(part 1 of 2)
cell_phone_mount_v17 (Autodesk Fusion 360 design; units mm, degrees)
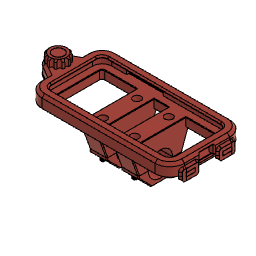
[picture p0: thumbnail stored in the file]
sketch "Skizze1" plane through (0, 0, 0) normal (0, 0, 1) x axis (1, 0, 0)
  line L1 (-75.65, 36.95) -> (75.65, 36.95)
  line L2 (-75.65, -36.95) -> (-75.65, 36.95)
  line L3 (75.65, -36.95) -> (-75.65, -36.95)
  line L4 (75.65, 36.95) -> (75.65, -36.95)
  line L5 (-75.65, -36.95) -> (75.65, 36.95)
  line L6 (75.65, -36.95) -> (-75.65, 36.95)
  point P1 (0, 0)
  point P2 (0, 0)
  point P7 (0, 0)
  point P3 (75.65, 36.95)
  point P6 (75.65, -36.95)
  point P5 (-75.65, -36.95)
  coincident P1 P2
  horizontal L1
  perpendicular L1 L2
  parallel L1 L3
  parallel L2 L4
  coincident L5 P7
  coincident L6 P7
  coincident P2 P7
  dimension "d2" distance P3 P6 = 73.9
  dimension "d3" distance P5 P6 = 151.3
extrude "Extrusion1" new body sketch "Skizze1" profile of L1 L2 L3 L4 along normal blind 9.3
fillet "Abrundung1" radius 11
component_from_bodies "Körper->Berechn"
sketch "Skizze1" plane through (0, 0, 9.3) normal (0, 0, 1) x axis (-1, 0, 0)
  line L1 (75.65, 25.95) -> (75.65, -25.95)
  line L2 (-64.65, 36.95) -> (64.65, 36.95)
  line L3 (-75.65, -25.95) -> (-75.65, 25.95)
  line L4 (64.65, -36.95) -> (-64.65, -36.95)
  line L5 (-64.65, 32.15) -> (64.65, 32.15)
  line L6 (-70.85, -25.95) -> (-70.85, 25.95)
  line L7 (64.65, -32.15) -> (-64.65, -32.15)
  line L8 (70.85, 25.95) -> (70.85, -25.95)
  line L9 (64.65, -40.25) -> (-64.65, -40.25)
  line L10 (78.95, 25.95) -> (78.95, -25.95)
  line L11 (-64.65, 40.25) -> (64.65, 40.25)
  line L12 (-78.95, -25.95) -> (-78.95, 25.95)
  arc A1 centre (64.65, -25.95) radius 11 clockwise from (75.65, -25.95) to (64.65, -36.95)
  arc A2 centre (64.65, 25.95) radius 11 clockwise from (64.65, 36.95) to (75.65, 25.95)
  arc A3 centre (-64.65, 25.95) radius 11 clockwise from (-75.65, 25.95) to (-64.65, 36.95)
  arc A4 centre (-64.65, -25.95) radius 11 clockwise from (-64.65, -36.95) to (-75.65, -25.95)
  arc A5 centre (-64.65, 25.95) radius 6.2 clockwise from (-70.85, 25.95) to (-64.65, 32.15)
  arc A6 centre (-64.65, -25.95) radius 6.2 clockwise from (-64.65, -32.15) to (-70.85, -25.95)
  arc A7 centre (64.65, -25.95) radius 6.2 clockwise from (70.85, -25.95) to (64.65, -32.15)
  arc A8 centre (64.65, 25.95) radius 6.2 clockwise from (64.65, 32.15) to (70.85, 25.95)
  arc A9 centre (64.65, -25.95) radius 14.3 clockwise from (78.95, -25.95) to (64.65, -40.25)
  arc A10 centre (64.65, 25.95) radius 14.3 clockwise from (64.65, 40.25) to (78.95, 25.95)
  arc A11 centre (-64.65, 25.95) radius 14.3 clockwise from (-78.95, 25.95) to (-64.65, 40.25)
  arc A12 centre (-64.65, -25.95) radius 14.3 clockwise from (-64.65, -40.25) to (-78.95, -25.95)
  point P1 (0, 0)
  point P14 (0, 0)
  point P15 (0, 0)
  coincident P1 P14
  coincident P1 P15
  dimension "d15" = -4.8
  dimension "d16" = 3.3
extrude "Extrusion1" new body sketch "Skizze1" along normal blind 2
sketch "Skizze2" plane through (0, 0, 9.3) normal (0, 0, -1) x axis (1, 0, 0)
  line L1 (64.65, 32.15) -> (-64.65, 32.15)
  line L2 (70.85, -25.95) -> (70.85, 25.95)
  line L3 (-64.65, -32.15) -> (64.65, -32.15)
  line L4 (-70.85, 25.95) -> (-70.85, -25.95)
  line L5 (78.95, 25.95) -> (78.95, -25.95)
  line L6 (-64.65, 40.25) -> (64.65, 40.25)
  line L7 (-78.95, -25.95) -> (-78.95, 25.95)
  line L8 (64.65, -40.25) -> (-64.65, -40.25)
  line L9 (64.65, -37.05) -> (-64.65, -37.05)
  line L10 (75.75, 25.95) -> (75.75, -25.95)
  line L11 (-64.65, 37.05) -> (64.65, 37.05)
  line L12 (-75.75, -25.95) -> (-75.75, 25.95)
  arc A1 centre (-64.65, 25.95) radius 6.2 clockwise from (-70.85, 25.95) to (-64.65, 32.15)
  arc A2 centre (64.65, 25.95) radius 6.2 clockwise from (64.65, 32.15) to (70.85, 25.95)
  arc A3 centre (64.65, -25.95) radius 6.2 clockwise from (70.85, -25.95) to (64.65, -32.15)
  arc A4 centre (-64.65, -25.95) radius 6.2 clockwise from (-64.65, -32.15) to (-70.85, -25.95)
  arc A5 centre (64.65, -25.95) radius 14.3 clockwise from (78.95, -25.95) to (64.65, -40.25)
  arc A6 centre (64.65, 25.95) radius 14.3 clockwise from (64.65, 40.25) to (78.95, 25.95)
  arc A7 centre (-64.65, 25.95) radius 14.3 clockwise from (-78.95, 25.95) to (-64.65, 40.25)
  arc A8 centre (-64.65, -25.95) radius 14.3 clockwise from (-64.65, -40.25) to (-78.95, -25.95)
  arc A9 centre (64.65, -25.95) radius 11.1 clockwise from (75.75, -25.95) to (64.65, -37.05)
  arc A10 centre (64.65, 25.95) radius 11.1 clockwise from (64.65, 37.05) to (75.75, 25.95)
  arc A11 centre (-64.65, 25.95) radius 11.1 clockwise from (-75.75, 25.95) to (-64.65, 37.05)
  arc A12 centre (-64.65, -25.95) radius 11.1 clockwise from (-64.65, -37.05) to (-75.75, -25.95)
  dimension "d19" = -3.2
extrude "Extrusion2" add sketch "Skizze2" profile of A5 L5 A6 L6 A7 L7 A8 L8 A12 L9 L12 A9 L11 L10 A10 A11 to an object
sketch "Skizze1" plane through (0, 0, 0) normal (0, 0, -1) x axis (1, 0, 0)
  line L1 (64.65, -36.95) -> (-64.65, -36.95)
  line L2 (75.65, 25.95) -> (75.65, -25.95)
  line L3 (-64.65, 36.95) -> (64.65, 36.95)
  line L4 (-75.65, -25.95) -> (-75.65, 25.95)
  line L5 (-64.65, -37.05) -> (64.65, -37.05)
  line L6 (-75.75, 25.95) -> (-75.75, -25.95)
  line L7 (64.65, 37.05) -> (-64.65, 37.05)
  line L8 (75.75, -25.95) -> (75.75, 25.95)
  line L9 (64.65, -40.25) -> (-64.65, -40.25)
  line L10 (78.95, 25.95) -> (78.95, -25.95)
  line L11 (-64.65, 40.25) -> (64.65, 40.25)
  line L12 (-78.95, -25.95) -> (-78.95, 25.95)
  line L13 (64.65, -28.95) -> (-64.65, -28.95)
  line L14 (67.65, 25.95) -> (67.65, -25.95)
  line L15 (-64.65, 28.95) -> (64.65, 28.95)
  line L16 (-67.65, -25.95) -> (-67.65, 25.95)
  line L17 (-28.15, -28.95) -> (-28.15, 28.95)
  line L18 (-8.15, -28.95) -> (-8.15, 28.95)
  line L19 (8.15, -28.95) -> (8.15, 28.95)
  line L20 (28.15, -28.95) -> (28.15, 28.95)
  arc A1 centre (-64.65, -25.95) radius 11 clockwise from (-64.65, -36.95) to (-75.65, -25.95)
  arc A2 centre (64.65, -25.95) radius 11 clockwise from (75.65, -25.95) to (64.65, -36.95)
  arc A3 centre (64.65, 25.95) radius 11 clockwise from (64.65, 36.95) to (75.65, 25.95)
  arc A4 centre (-64.65, 25.95) radius 11 clockwise from (-75.65, 25.95) to (-64.65, 36.95)
  arc A5 centre (-64.65, -25.95) radius 11.1 clockwise from (-64.65, -37.05) to (-75.75, -25.95)
  arc A6 centre (-64.65, 25.95) radius 11.1 clockwise from (-75.75, 25.95) to (-64.65, 37.05)
  arc A7 centre (64.65, 25.95) radius 11.1 clockwise from (64.65, 37.05) to (75.75, 25.95)
  arc A8 centre (64.65, -25.95) radius 11.1 clockwise from (75.75, -25.95) to (64.65, -37.05)
  arc A9 centre (-64.65, -25.95) radius 14.3 clockwise from (-64.65, -40.25) to (-78.95, -25.95)
  arc A10 centre (64.65, -25.95) radius 14.3 clockwise from (78.95, -25.95) to (64.65, -40.25)
  arc A11 centre (64.65, 25.95) radius 14.3 clockwise from (64.65, 40.25) to (78.95, 25.95)
  arc A12 centre (-64.65, 25.95) radius 14.3 clockwise from (-78.95, 25.95) to (-64.65, 40.25)
  arc A13 centre (64.65, -25.95) radius 3 clockwise from (67.65, -25.95) to (64.65, -28.95)
  arc A14 centre (64.65, 25.95) radius 3 clockwise from (64.65, 28.95) to (67.65, 25.95)
  arc A15 centre (-64.65, 25.95) radius 3 clockwise from (-67.65, 25.95) to (-64.65, 28.95)
  arc A16 centre (-64.65, -25.95) radius 3 clockwise from (-64.65, -28.95) to (-67.65, -25.95)
  point P46 (-28.15, 28.95)
  point P47 (-28.15, -28.95)
  point P48 (-8.15, 28.95)
  point P49 (-8.15, -28.95)
  point P50 (8.15, 28.95)
  point P51 (8.15, -28.95)
  point P52 (28.15, 28.95)
  point P53 (28.15, -28.95)
  coincident L15 P46
  coincident L13 P47
  perpendicular L13 L17
  coincident L15 P48
  coincident L13 P49
  perpendicular L13 L18
  coincident L15 P50
  coincident L13 P51
  perpendicular L13 L19
  coincident L15 P52
  coincident L13 P53
  perpendicular L13 L20
  dimension "d22" = -8
  dimension "d25" distance L17 L18 = 20
  dimension "d26" distance L19 L20 = 20 (= "d25")
  dimension "d27" distance L16 L17 = 39.5
  dimension "d28" distance L14 L20 = 39.5 (= "d27")
  dimension "d132" distance L17 L20 = 56.3
extrude "Extrusion1" new body sketch "Skizze1" along normal blind 2
sketch "Skizze2" plane through (0, 0, -2) normal (0, 0, -1) x axis (1, 0, 0)
  line L1 (28.15, 28.95) -> (28.15, -28.95)
  line L2 (64.65, 28.95) -> (28.15, 28.95)
  line L3 (67.65, -25.95) -> (67.65, 25.95)
  line L4 (28.15, -28.95) -> (64.65, -28.95)
  line L5 (-28.15, 28.95) -> (-64.65, 28.95)
  line L6 (-28.15, -28.95) -> (-28.15, 28.95)
  line L7 (-64.65, -28.95) -> (-28.15, -28.95)
  line L8 (-67.65, 25.95) -> (-67.65, -25.95)
  line L9 (-8.15, 28.95) -> (-8.15, -28.95)
  line L10 (8.15, 28.95) -> (-8.15, 28.95)
  line L11 (8.15, -28.95) -> (8.15, 28.95)
  line L12 (-8.15, -28.95) -> (8.15, -28.95)
  line L13 (-78.95, -25.95) -> (-78.95, 25.95)
  line L14 (64.65, -40.25) -> (-64.65, -40.25)
  line L15 (78.95, 25.95) -> (78.95, -25.95)
  line L16 (-64.65, 40.25) -> (64.65, 40.25)
  line L17 (-122.0069, 0) -> (0, 0)
  line L18 (-8.15, 25) -> (-28.15, 25)
  line L19 (28.15, 25) -> (8.15, 25)
  line L20 (-8.15, -25) -> (-28.15, -25)
  line L21 (28.15, -25) -> (8.15, -25)
  arc A1 centre (64.65, 25.95) radius 3 clockwise from (64.65, 28.95) to (67.65, 25.95)
  arc A2 centre (64.65, -25.95) radius 3 clockwise from (67.65, -25.95) to (64.65, -28.95)
  arc A3 centre (-64.65, 25.95) radius 3 clockwise from (-67.65, 25.95) to (-64.65, 28.95)
  arc A4 centre (-64.65, -25.95) radius 3 clockwise from (-64.65, -28.95) to (-67.65, -25.95)
  arc A5 centre (-64.65, -25.95) radius 14.3 clockwise from (-64.65, -40.25) to (-78.95, -25.95)
  arc A6 centre (64.65, -25.95) radius 14.3 clockwise from (78.95, -25.95) to (64.65, -40.25)
  arc A7 centre (64.65, 25.95) radius 14.3 clockwise from (64.65, 40.25) to (78.95, 25.95)
  arc A8 centre (-64.65, 25.95) radius 14.3 clockwise from (-78.95, 25.95) to (-64.65, 40.25)
  point P1 (0, 0)
  point P30 (0, 0)
  point P32 (-28.15, 25)
  point P33 (-8.15, 25)
  point P34 (8.15, 25)
  point P35 (28.15, 25)
  point P36 (-28.15, -25)
  point P37 (-8.15, -25)
  point P38 (8.15, -25)
  point P39 (28.15, -25)
  coincident P1 P30
  perpendicular L8 L17
  coincident L6 P32
  coincident L9 P33
  perpendicular L9 L18
  coincident L11 P34
  coincident L1 P35
  perpendicular L11 L19
  coincident L6 P36
  coincident L9 P37
  perpendicular L9 L20
  coincident L11 P38
  coincident L1 P39
  perpendicular L1 L21
  symmetric L17 L18 L20
  collinear L18 L19
  collinear L20 L21
  dimension "d29" distance L18 L20 = 50
extrude "Extrusion2" add sketch "Skizze2" profile of L1 L6 L9 L11 L18 L19 L20 L21 along normal blind 30
sketch "Skizze1" plane through (0, 0, -32) normal (0, 0, -1) x axis (1, 0, 0)
  line L1 (-28.15, -25) -> (-28.15, 25)
  line L2 (-8.15, -25) -> (-28.15, -25)
  line L3 (-8.15, 25) -> (-8.15, -25)
  line L4 (-28.15, 25) -> (-8.15, 25)
  line L5 (8.15, -25) -> (8.15, 25)
  line L6 (28.15, -25) -> (8.15, -25)
  line L7 (28.15, 25) -> (28.15, -25)
  line L8 (8.15, 25) -> (28.15, 25)
extrude "Extrusion1" new body sketch "Skizze1" along normal blind 18
sketch "Skizze2" plane through (-28.15, 0, 0) normal (-1, 0, 0) x axis (0, -1, 0)
  line L1 (-25, -32) -> (25, -32)
  line L2 (-25, -50) -> (-25, -32)
  line L3 (25, -50) -> (-25, -50)
  line L4 (25, -32) -> (25, -50)
  circle C1 centre (0, -32) radius 14
  point P6 (0, -32)
  midpoint L1 P6
  dimension "d34" diameter C1 = 28
extrude "Extrusion2" cut sketch "Skizze2" profile of L1 C1 no distance stored
sketch "Skizze3" plane through (-28.15, 0, 0) normal (-1, 0, 0) x axis (0, -1, 0)
  line L1 (-28.95, 0) -> (28.95, 0)
  line L2 (-28.95, -2) -> (-28.95, 0)
  line L3 (-25, -2) -> (-28.95, -2)
  line L4 (-25, -32) -> (-25, -2)
  line L5 (25, -32) -> (-25, -32)
  line L6 (25, -2) -> (25, -32)
  line L7 (28.95, -2) -> (25, -2)
  line L8 (28.95, 0) -> (28.95, -2)
  arc A1 centre (0, -32) radius 14 clockwise from (14, -32) to (-14, -32)
  circle C1 centre (0, -32) radius 14
  point P11 (14, -32)
  concentric A1 C1
  coincident P11 C1
extrude "Extrusion3" cut sketch "Skizze3" profile of L5 C1 no distance stored
sketch "Skizze4" plane through (0, 0, -32) normal (0, 0, -1) x axis (1, 0, 0)
  line L1 (-28.15, -14) -> (-8.15, -14)
  line L2 (-28.15, -25) -> (-28.15, -14)
  line L3 (-8.15, -25) -> (-28.15, -25)
  line L4 (-8.15, -14) -> (-8.15, -25)
  line L5 (-28.15, 25) -> (-8.15, 25)
  line L6 (-8.15, 14) -> (-28.15, 14)
  line L7 (-8.15, 25) -> (-8.15, 14)
  line L8 (-28.15, 25) -> (-8.15, 25)
  line L9 (-28.15, 14) -> (-28.15, 25)
  line L10 (8.15, -14) -> (28.15, -14)
  line L11 (8.15, -25) -> (8.15, -14)
  line L12 (28.15, -25) -> (8.15, -25)
  line L13 (28.15, -14) -> (28.15, -25)
  line L14 (28.15, 14) -> (8.15, 14)
  line L15 (28.15, 14) -> (8.15, 14)
  line L16 (28.15, 25) -> (28.15, 14)
  line L17 (8.15, 25) -> (28.15, 25)
  line L18 (8.15, 14) -> (8.15, 25)
  point P6 (-18.15, -19.5)
  point P9 (-18.15, 19.5)
  point P7 (18.15, -19.5)
  point P8 (18.15, 19.5)
  point P12 (-28.15, 14)
  point P13 (-8.15, 14)
  vertical P6 P9
  vertical P7 P8
  dimension "d37" distance P9 L8 = 5.5 (= "11.00 mm / 2")
  dimension "d38" distance L5 L6 = 11
  dimension "d39" distance L1 P6 = 5.5 (= "d37")
  dimension "d40" distance P8 L17 = 5.5 (= "d37")
  dimension "d41" distance P7 L12 = 5.5 (= "d37")
  dimension "d42" distance P12 P13 = 20
  dimension "d43" distance L4 P6 = 10 (= "20.00 mm / 2")
  dimension "d44" distance P7 L11 = 10 (= "20.00 mm / 2")
sketch "Skizze3" plane through (0, 0, -32) normal (0, 0, 1) x axis (-1, 0, 0)
  line L1 (8.15, -14) -> (28.15, -14)
  line L2 (8.15, -25) -> (8.15, -14)
  line L3 (28.15, -25) -> (8.15, -25)
  line L4 (28.15, -14) -> (28.15, -25)
hole "Bohrung1" HoleDepth 17 HoleDiameter 4.234 TipAngle 180
sketch "Skizze5" plane through (0, 0, 0) normal (0, 0, 1) x axis (-1, 0, 0)
  line L1 (-28.15, -28.95) -> (-28.15, 28.95)
  line L2 (-64.65, -28.95) -> (-28.15, -28.95)
  line L3 (-67.65, 25.95) -> (-67.65, -25.95)
  line L4 (-28.15, 28.95) -> (-64.65, 28.95)
  line L5 (67.65, -25.95) -> (67.65, 25.95)
  line L6 (28.15, -28.95) -> (64.65, -28.95)
  line L7 (28.15, 28.95) -> (28.15, -28.95)
  line L8 (64.65, 28.95) -> (28.15, 28.95)
  line L9 (8.15, -28.95) -> (8.15, 28.95)
  line L10 (-8.15, -28.95) -> (8.15, -28.95)
  line L11 (-8.15, 28.95) -> (-8.15, -28.95)
  line L12 (8.15, 28.95) -> (-8.15, 28.95)
  line L13 (78.95, 25.95) -> (78.95, -25.95)
  line L14 (-64.65, 40.25) -> (64.65, 40.25)
  line L15 (-78.95, -25.95) -> (-78.95, 25.95)
  line L16 (64.65, -40.25) -> (-64.65, -40.25)
  arc A1 centre (-64.65, -25.95) radius 3 clockwise from (-64.65, -28.95) to (-67.65, -25.95)
  arc A2 centre (-64.65, 25.95) radius 3 clockwise from (-67.65, 25.95) to (-64.65, 28.95)
  arc A3 centre (64.65, 25.95) radius 3 clockwise from (64.65, 28.95) to (67.65, 25.95)
  arc A4 centre (64.65, -25.95) radius 3 clockwise from (67.65, -25.95) to (64.65, -28.95)
  arc A5 centre (64.65, 25.95) radius 14.3 clockwise from (64.65, 40.25) to (78.95, 25.95)
  arc A6 centre (-64.65, 25.95) radius 14.3 clockwise from (-78.95, 25.95) to (-64.65, 40.25)
  arc A7 centre (-64.65, -25.95) radius 14.3 clockwise from (-64.65, -40.25) to (-78.95, -25.95)
  arc A8 centre (64.65, -25.95) radius 14.3 clockwise from (78.95, -25.95) to (64.65, -40.25)
hole "Bohrung1" HoleDepth 32 HoleDiameter 5.5 TipAngle 180 CBDepth 12 CBDiameter 9
sketch "Skizze3" plane through (0, 0, -2) normal (0, 0, -1) x axis (1, 0, 0)
  line L1 (8.15, -25) -> (28.15, -25)
  line L2 (8.15, -28.95) -> (8.15, -25)
  line L3 (-8.15, -28.95) -> (8.15, -28.95)
  line L4 (-8.15, -25) -> (-8.15, -28.95)
  line L5 (-28.15, -25) -> (-8.15, -25)
  line L6 (-28.15, -28.95) -> (-28.15, -25)
  line L7 (-64.65, -28.95) -> (-28.15, -28.95)
  line L8 (-67.65, 25.95) -> (-67.65, -25.95)
  line L9 (-28.15, 28.95) -> (-64.65, 28.95)
  line L10 (-28.15, 25) -> (-28.15, 28.95)
  line L11 (-8.15, 25) -> (-28.15, 25)
  line L12 (-8.15, 28.95) -> (-8.15, 25)
  line L13 (8.15, 28.95) -> (-8.15, 28.95)
  line L14 (8.15, 25) -> (8.15, 28.95)
  line L15 (28.15, 25) -> (8.15, 25)
  line L16 (28.15, 28.95) -> (28.15, 25)
  line L17 (64.65, 28.95) -> (28.15, 28.95)
  line L18 (67.65, -25.95) -> (67.65, 25.95)
  line L19 (28.15, -28.95) -> (64.65, -28.95)
  line L20 (28.15, -25) -> (28.15, -28.95)
  line L21 (-78.95, -25.95) -> (-78.95, 25.95)
  line L22 (64.65, -40.25) -> (-64.65, -40.25)
  line L23 (78.95, 25.95) -> (78.95, -25.95)
  line L24 (-64.65, 40.25) -> (64.65, 40.25)
  line L25 (-81.55, -25.95) -> (-81.55, 25.95)
  line L26 (64.65, -42.85) -> (-64.65, -42.85)
  line L27 (81.55, 25.95) -> (81.55, -25.95)
  line L28 (-64.65, 42.85) -> (64.65, 42.85)
  arc A1 centre (-64.65, -25.95) radius 3 clockwise from (-64.65, -28.95) to (-67.65, -25.95)
  arc A2 centre (-64.65, 25.95) radius 3 clockwise from (-67.65, 25.95) to (-64.65, 28.95)
  arc A3 centre (64.65, 25.95) radius 3 clockwise from (64.65, 28.95) to (67.65, 25.95)
  arc A4 centre (64.65, -25.95) radius 3 clockwise from (67.65, -25.95) to (64.65, -28.95)
  arc A5 centre (-64.65, -25.95) radius 14.3 clockwise from (-64.65, -40.25) to (-78.95, -25.95)
  arc A6 centre (64.65, -25.95) radius 14.3 clockwise from (78.95, -25.95) to (64.65, -40.25)
  arc A7 centre (64.65, 25.95) radius 14.3 clockwise from (64.65, 40.25) to (78.95, 25.95)
  arc A8 centre (-64.65, 25.95) radius 14.3 clockwise from (-78.95, 25.95) to (-64.65, 40.25)
  arc A9 centre (-64.65, -25.95) radius 16.9 clockwise from (-64.65, -42.85) to (-81.55, -25.95)
  arc A10 centre (64.65, -25.95) radius 16.9 clockwise from (81.55, -25.95) to (64.65, -42.85)
  arc A11 centre (64.65, 25.95) radius 16.9 clockwise from (64.65, 42.85) to (81.55, 25.95)
  arc A12 centre (-64.65, 25.95) radius 16.9 clockwise from (-81.55, 25.95) to (-64.65, 42.85)
  dimension "d53" = 2.6
extrude "Extrusion3" add sketch "Fase7" profile of L21 A5 L22 A6 L23 A7 L24 A8 A12 L27 L26 L25 A9 A10 A11 L28 to an object
sketch "Skizze4" plane through (0, 0, -2) normal (0, 0, -1) x axis (1, 0, 0)
  line L1 (64.65, 40.25) -> (-64.65, 40.25)
  line L2 (78.95, -25.95) -> (78.95, 25.95)
  line L3 (-64.65, -40.25) -> (64.65, -40.25)
  line L4 (-78.95, 25.95) -> (-78.95, -25.95)
  line L5 (-81.55, -25.95) -> (-81.55, 25.95)
  line L6 (64.65, -42.85) -> (-64.65, -42.85)
  line L7 (81.55, 25.95) -> (81.55, -25.95)
  line L8 (-64.65, 42.85) -> (64.65, 42.85)
  line L9 (64.65, 40.45) -> (-64.65, 40.45)
  line L10 (79.15, -25.95) -> (79.15, 25.95)
  line L11 (-64.65, -40.45) -> (64.65, -40.45)
  line L12 (-79.15, 25.95) -> (-79.15, -25.95)
  arc A1 centre (-64.65, 25.95) radius 14.3 clockwise from (-78.95, 25.95) to (-64.65, 40.25)
  arc A2 centre (64.65, 25.95) radius 14.3 clockwise from (64.65, 40.25) to (78.95, 25.95)
  arc A3 centre (64.65, -25.95) radius 14.3 clockwise from (78.95, -25.95) to (64.65, -40.25)
  arc A4 centre (-64.65, -25.95) radius 14.3 clockwise from (-64.65, -40.25) to (-78.95, -25.95)
  arc A5 centre (-64.65, 25.95) radius 16.9 clockwise from (-81.55, 25.95) to (-64.65, 42.85)
  arc A6 centre (-64.65, -25.95) radius 16.9 clockwise from (-64.65, -42.85) to (-81.55, -25.95)
  arc A7 centre (64.65, -25.95) radius 16.9 clockwise from (81.55, -25.95) to (64.65, -42.85)
  arc A8 centre (64.65, 25.95) radius 16.9 clockwise from (64.65, 42.85) to (81.55, 25.95)
  arc A9 centre (64.65, 25.95) radius 14.5 clockwise from (64.65, 40.45) to (79.15, 25.95)
  arc A10 centre (64.65, -25.95) radius 14.5 clockwise from (79.15, -25.95) to (64.65, -40.45)
  arc A11 centre (-64.65, -25.95) radius 14.5 clockwise from (-64.65, -40.45) to (-79.15, -25.95)
  arc A12 centre (-64.65, 25.95) radius 14.5 clockwise from (-79.15, 25.95) to (-64.65, 40.45)
  dimension "d56" = 0.2
extrude "Extrusion4" cut sketch "Skizze4" profile of A1 L1 A2 L2 A3 L3 A4 L4 L9 A9 A10 L10 L12 L11 A11 A12 to an object
sketch "Skizze7" plane through (0, 0, 11.3) normal (0, 0, 1) x axis (-1, 0, 0)
  line L1 (81.55, 25.95) -> (81.55, -25.95)
  line L2 (-64.65, 42.85) -> (64.65, 42.85)
  line L3 (-81.55, -25.95) -> (-81.55, 25.95)
  line L4 (64.65, -42.85) -> (-64.65, -42.85)
  line L5 (70.85, -25.95) -> (70.85, 25.95)
  line L6 (-64.65, -32.15) -> (64.65, -32.15)
  line L7 (-70.85, 25.95) -> (-70.85, -25.95)
  line L8 (64.65, 32.15) -> (-64.65, 32.15)
  line L9 (127.128, 0) -> (0, 0)
  line L10 (81.55, -19.2258) -> (95.35, -11.2583)
  line L11 (81.55, 19.2258) -> (95.35, 11.2583)
  arc A1 centre (64.65, 25.95) radius 16.9 clockwise from (64.65, 42.85) to (81.55, 25.95)
  arc A2 centre (-64.65, 25.95) radius 16.9 clockwise from (-81.55, 25.95) to (-64.65, 42.85)
  arc A3 centre (-64.65, -25.95) radius 16.9 clockwise from (-64.65, -42.85) to (-81.55, -25.95)
  arc A4 centre (64.65, -25.95) radius 16.9 clockwise from (81.55, -25.95) to (64.65, -42.85)
  arc A5 centre (64.65, 25.95) radius 6.2 clockwise from (64.65, 32.15) to (70.85, 25.95)
  arc A6 centre (64.65, -25.95) radius 6.2 clockwise from (70.85, -25.95) to (64.65, -32.15)
  arc A7 centre (-64.65, -25.95) radius 6.2 clockwise from (-64.65, -32.15) to (-70.85, -25.95)
  arc A8 centre (-64.65, 25.95) radius 6.2 clockwise from (-70.85, 25.95) to (-64.65, 32.15)
  circle C1 centre (88.85, 0) radius 13
  circle C2 centre (88.85, 0) radius 3
  point P1 (0, 0)
  point P23 (0, 0)
  point P22 (88.85, 0)
  point P25 (95.35, -11.2583)
  point P26 (81.55, -19.2258)
  point P27 (95.35, 11.2583)
  point P28 (81.55, 19.2258)
  point P29 (88.85, 0)
  coincident P1 P23
  horizontal L9
  coincident P22 L9
  coincident C1 P25
  coincident L1 P26
  coincident C1 P27
  coincident L1 P28
  tangent C1 L11
  tangent C1 L10
  concentric C1 C2
  dimension "d92" diameter C1 = 26
  dimension "d94" angle L1 L11 = 120
  dimension "d95" angle L1 L10 = 120
  dimension "d98" diameter C2 = 6
  dimension "d99" distance L5 P29 = 18
extrude "Extrusion7" add sketch "Skizze7" profile of L1 C1 L10 L11 C2 against normal blind 13.3
chamfer "Fase1" distance 3
sketch "Skizze2" plane through (78.95, 0, 0) normal (1, 0, 0) x axis (0, 1, 0)
  line L1 (-25.95, 0) -> (25.95, 0)
  line L2 (-25.95, -2) -> (-25.95, 0)
  line L3 (25.95, -2) -> (-25.95, -2)
  line L4 (25.95, 0) -> (25.95, -2)
  line L5 (-15.95, 0) -> (-25.95, 0)
  line L6 (-15.95, -2) -> (-15.95, 0)
  line L7 (-25.95, -2) -> (-15.95, -2)
  line L8 (-25.95, 0) -> (-25.95, -2)
  line L9 (15.95, 0) -> (25.95, 0)
  line L10 (15.95, -2) -> (15.95, 0)
  line L11 (25.95, -2) -> (15.95, -2)
  line L12 (25.95, 0) -> (25.95, -2)
  point P8 (-15.95, -2)
  point P3 (-25.95, 0)
  point P6 (-25.95, 0)
  point P12 (15.95, -2)
  point P2 (25.95, 0)
  point P10 (25.95, 0)
  point P7 (-15.95, 0)
  point P11 (15.95, 0)
  horizontal L5
  vertical L6
  horizontal L7
  vertical L8
  coincident L3 P8
  coincident P3 P6
  horizontal L9
  vertical L10
  horizontal L11
  vertical L12
  coincident L3 P12
  coincident P2 P10
  dimension "d60" distance P6 P7 = 10
  dimension "d61" distance P10 P11 = 10
extrude "Extrusion4" add sketch "Skizze2" along normal blind 4.8
sketch "Skizze6" plane through (0, 0, -2) normal (0, 0, -1) x axis (1, 0, 0)
  line L1 (8.15, -25) -> (28.15, -25)
  line L2 (8.15, -28.95) -> (8.15, -25)
  line L3 (-8.15, -28.95) -> (8.15, -28.95)
  line L4 (-8.15, -25) -> (-8.15, -28.95)
  line L5 (-28.15, -25) -> (-8.15, -25)
  line L6 (-28.15, -28.95) -> (-28.15, -25)
  line L7 (-64.65, -28.95) -> (-28.15, -28.95)
  line L8 (-67.65, 25.95) -> (-67.65, -25.95)
  line L9 (-28.15, 28.95) -> (-64.65, 28.95)
  line L10 (-28.15, 25) -> (-28.15, 28.95)
  line L11 (-8.15, 25) -> (-28.15, 25)
  line L12 (-8.15, 28.95) -> (-8.15, 25)
  line L13 (8.15, 28.95) -> (-8.15, 28.95)
  line L14 (8.15, 25) -> (8.15, 28.95)
  line L15 (28.15, 25) -> (8.15, 25)
  line L16 (28.15, 28.95) -> (28.15, 25)
  line L17 (64.65, 28.95) -> (28.15, 28.95)
  line L18 (67.65, -25.95) -> (67.65, 25.95)
  line L19 (28.15, -28.95) -> (64.65, -28.95)
  line L20 (28.15, -25) -> (28.15, -28.95)
  line L21 (-78.95, -25.95) -> (-78.95, 25.95)
  line L22 (64.65, -40.25) -> (-64.65, -40.25)
  line L23 (83.75, -25.95) -> (78.95, -25.95)
  line L24 (83.75, -15.95) -> (83.75, -25.95)
  line L25 (78.95, -15.95) -> (83.75, -15.95)
  line L26 (78.95, 15.95) -> (78.95, -15.95)
  line L27 (83.75, 15.95) -> (78.95, 15.95)
  line L28 (83.75, 25.95) -> (83.75, 15.95)
  line L29 (78.95, 25.95) -> (83.75, 25.95)
  line L30 (-64.65, 40.25) -> (64.65, 40.25)
  line L31 (73.75, 25.95) -> (83.75, 25.95)
  line L32 (73.75, 15.95) -> (73.75, 25.95)
  line L33 (83.75, 15.95) -> (73.75, 15.95)
  line L34 (83.75, 25.95) -> (83.75, 15.95)
  line L35 (73.75, -15.95) -> (83.75, -15.95)
  line L36 (73.75, -25.95) -> (73.75, -15.95)
  line L37 (83.75, -25.95) -> (73.75, -25.95)
  line L38 (83.75, -15.95) -> (83.75, -25.95)
  arc A1 centre (-64.65, -25.95) radius 3 clockwise from (-64.65, -28.95) to (-67.65, -25.95)
  arc A2 centre (-64.65, 25.95) radius 3 clockwise from (-67.65, 25.95) to (-64.65, 28.95)
  arc A3 centre (64.65, 25.95) radius 3 clockwise from (64.65, 28.95) to (67.65, 25.95)
  arc A4 centre (64.65, -25.95) radius 3 clockwise from (67.65, -25.95) to (64.65, -28.95)
  arc A5 centre (-64.65, -25.95) radius 14.3 clockwise from (-64.65, -40.25) to (-78.95, -25.95)
  arc A6 centre (64.65, -25.95) radius 14.3 clockwise from (78.95, -25.95) to (64.65, -40.25)
  arc A7 centre (64.65, 25.95) radius 14.3 clockwise from (64.65, 40.25) to (78.95, 25.95)
  arc A8 centre (-64.65, 25.95) radius 14.3 clockwise from (-78.95, 25.95) to (-64.65, 40.25)
  point P40 (83.75, 25.95)
  point P44 (83.75, 25.95)
  point P36 (83.75, -15.95)
  point P48 (83.75, -15.95)
  horizontal L31
  vertical L32
  horizontal L33
  vertical L34
  coincident P40 P44
  horizontal L35
  vertical L36
  horizontal L37
  vertical L38
  coincident P36 P48
  collinear L32 L36
  dimension "d64" distance L32 L34 = 10
extrude "Extrusion5" add sketch "Skizze6" profile of L23 L24 L25 L27 L28 L29 L31 L32 L33 L34 L35 L36 L37 L38 along normal blind 2
chamfer "Fase1" distance 2
work_plane "Arbeitsebene" AlongDistance -6
sketch "Skizze5" plane through (0, 0, 4) normal (0, 0, -1) x axis (1, 0, 0)
  line L1 (-64.65, -40.45) -> (64.65, -40.45)
  line L2 (-79.15, 25.95) -> (-79.15, 8.6551)
  line L3 (64.65, 40.45) -> (-64.65, 40.45)
  line L4 (79.15, -25.95) -> (79.15, 25.95)
  line L5 (-81.55, -25.95) -> (-81.55, -19.2258)
  line L6 (64.65, -42.85) -> (-64.65, -42.85)
  line L7 (81.55, 25.95) -> (81.55, -25.95)
  line L8 (-64.65, 42.85) -> (64.65, 42.85)
  line L9 (-83.75, -25.95) -> (-83.75, 25.95)
  line L10 (64.65, -45.05) -> (-64.65, -45.05)
  line L11 (83.75, 25.95) -> (83.75, -25.95)
  line L12 (-64.65, 45.05) -> (64.65, 45.05)
  line L13 (75.75, 15.95) -> (75.75, 25.95)
  line L14 (83.75, 15.95) -> (75.75, 15.95)
  line L15 (83.75, 25.95) -> (83.75, 15.95)
  line L16 (75.75, 25.95) -> (83.75, 25.95)
  line L17 (75.75, -25.95) -> (75.75, -15.95)
  line L18 (83.75, -25.95) -> (75.75, -25.95)
  line L19 (83.75, -15.95) -> (83.75, -25.95)
  line L20 (75.75, -15.95) -> (83.75, -15.95)
  line L21 (81.55, 11.95) -> (83.75, 11.95)
  line L22 (81.55, -11.95) -> (83.75, -11.95)
  line L23 (81.0698, -29.95) -> (83.3265, -29.95)
  line L24 (81.0698, 29.95) -> (83.3265, 29.95)
  line L25 (78.5874, 29.95) -> (81.0698, 29.95)
  line L26 (78.5874, -29.95) -> (81.0698, -29.95)
  line L27 (79.15, 11.95) -> (81.55, 11.95)
  line L28 (79.15, -11.95) -> (81.55, -11.95)
  line L29 (-79.15, -8.6551) -> (-79.15, -25.95)
  line L30 (-81.55, 19.2258) -> (-81.55, 25.95)
  line L31 (-95.35, 11.2583) -> (-81.55, 19.2258)
  line L32 (-81.55, -19.2258) -> (-95.35, -11.2583)
  arc A1 centre (64.65, -25.95) radius 14.5 clockwise from (79.15, -25.95) to (64.65, -40.45)
  arc A2 centre (-64.65, -25.95) radius 14.5 clockwise from (-64.65, -40.45) to (-79.15, -25.95)
  arc A3 centre (-64.65, 25.95) radius 14.5 clockwise from (-79.15, 25.95) to (-64.65, 40.45)
  arc A4 centre (64.65, 25.95) radius 14.5 clockwise from (64.65, 40.45) to (79.15, 25.95)
  arc A5 centre (-64.65, 25.95) radius 16.9 clockwise from (-81.55, 25.95) to (-64.65, 42.85)
  arc A6 centre (-64.65, -25.95) radius 16.9 clockwise from (-64.65, -42.85) to (-81.55, -25.95)
  arc A7 centre (64.65, -25.95) radius 16.9 clockwise from (81.55, -25.95) to (64.65, -42.85)
  arc A8 centre (64.65, 25.95) radius 16.9 clockwise from (64.65, 42.85) to (81.55, 25.95)
  arc A9 centre (-64.65, 25.95) radius 19.1 clockwise from (-83.75, 25.95) to (-64.65, 45.05)
  arc A10 centre (-64.65, -25.95) radius 19.1 clockwise from (-64.65, -45.05) to (-83.75, -25.95)
  arc A11 centre (64.65, -25.95) radius 19.1 clockwise from (83.75, -25.95) to (64.65, -45.05)
  arc A12 centre (64.65, 25.95) radius 19.1 clockwise from (64.65, 45.05) to (83.75, 25.95)
  circle C1 centre (-88.85, 0) radius 3
  arc A13 centre (-88.85, 0) radius 13 clockwise from (-79.15, 8.6551) to (-79.15, -8.6551)
  arc A14 centre (-88.85, 0) radius 13 clockwise from (-95.35, -11.2583) to (-95.35, 11.2583)
  point P42 (83.75, 11.95)
  point P43 (81.55, 11.95)
  point P44 (83.75, -11.95)
  point P45 (81.55, -11.95)
  point P46 (83.3265, -29.95)
  point P47 (81.0698, -29.95)
  point P48 (83.3265, 29.95)
  point P49 (81.0698, 29.95)
  point P50 (78.5874, 29.95)
  point P52 (79.15, 11.95)
  point P53 (79.15, -11.95)
  coincident L11 P42
  coincident L7 P43
  perpendicular L7 L21
  coincident L11 P44
  coincident L7 P45
  perpendicular L7 L22
  coincident A11 P46
  coincident A7 P47
  parallel L22 L23
  coincident A12 P48
  coincident A8 P49
  parallel L23 L24
  coincident A4 P50
  parallel L24 L25
  parallel L23 L26
  coincident L4 P52
  perpendicular L4 L27
  coincident L4 P53
  perpendicular L4 L28
  concentric A5 A9
  parallel L5 L9
  concentric A6 A10
  parallel L6 L10
  concentric A7 A11
  parallel L7 L11
  concentric A8 A12
  parallel L8 L12
  tangent A9 L12
  tangent L10 A11
  tangent A10 L10
  tangent A9 L9
  tangent A12 L12
  tangent L9 A10
  tangent A11 L11
  tangent L11 A12
  dimension "d70" distance L20 L22 = 4
  dimension "d71" distance L14 L21 = 4 (= "d70")
  dimension "d72" distance L16 L24 = 4 (= "d70")
  dimension "d73" distance L18 L23 = 4 (= "d70")
extrude "Extrusion5" add sketch "Skizze5" profile of A1 A4 L4 A7 L7 A8 A12 L11 A11 L14 L15 L16 L18 L19 L20 L21 L22 L23 L24 L25 L26 L27 L28 to an object offset 4
split "Teilen1"
remove_body "Körper entfernen1"
remove_body "Körper entfernen2"
sketch "Skizze6" plane through (83.75, 0, 0) normal (1, 0, 0) x axis (0, 1, 0)
  line L1 (-15.95, 0) -> (-25.95, 0)
  line L2 (-15.95, -4) -> (-15.95, 0)
  line L3 (-25.95, -4) -> (-15.95, -4)
  line L4 (-25.95, -8) -> (-25.95, -4)
  line L5 (-11.95, -8) -> (-25.95, -8)
  line L6 (-11.95, 4) -> (-11.95, -8)
  line L7 (-25.95, 4) -> (-11.95, 4)
  line L8 (-25.95, 0) -> (-25.95, 4)
  line L9 (-15.95, -4) -> (-25.95, -4)
  line L10 (-15.95, 0) -> (-15.95, -4)
  line L11 (-25.95, 0) -> (-25.95, -4)
  line L12 (15.95, -4) -> (15.95, 0)
  line L13 (25.95, 0) -> (25.95, -4)
  line L14 (25.95, -4) -> (15.95, -4)
  line L15 (-25.95, 0) -> (-15.95, 0)
  line L16 (25.95, 0) -> (15.95, 0)
  line L17 (-26.15, -4.2) -> (-15.75, -4.2)
  line L18 (-26.15, 0.2) -> (-26.15, -4.2)
  line L19 (-15.75, 0.2) -> (-26.15, 0.2)
  line L20 (-15.75, -4.2) -> (-15.75, 0.2)
  line L21 (26.15, -4.2) -> (15.75, -4.2)
  line L22 (26.15, 0.2) -> (26.15, -4.2)
  line L23 (15.75, 0.2) -> (26.15, 0.2)
  line L24 (15.75, -4.2) -> (15.75, 0.2)
  point P12 (-15.95, 0)
  point P18 (-15.95, 0)
  point P13 (-25.95, 0)
  point P19 (-25.95, 0)
  point P14 (15.95, 0)
  point P20 (15.95, 0)
  point P17 (25.95, 0)
  point P21 (25.95, 0)
  coincident P12 P18
  coincident P13 P19
  coincident P14 P20
  coincident P17 P21
  horizontal L17
  vertical L18
  horizontal L19
  vertical L20
  horizontal L21
  vertical L22
  horizontal L23
  vertical L24
  dimension "d76" distance L16 L23 = 0.2 (= "d77")
  dimension "d77" distance L13 L22 = 0.2
  dimension "d78" distance L10 L20 = 0.2 (= "d77")
  dimension "d79" distance L11 L18 = 0.2 (= "d77")
  dimension "d80" distance L12 L24 = 0.2 (= "d77")
  dimension "d81" distance L14 L21 = 0.2 (= "d77")
  dimension "d82" distance L15 L19 = 0.2 (= "d77")
  dimension "d83" distance L9 L17 = 0.2 (= "d77")
extrude "Extrusion1" cut sketch "Skizze6" profile of L1 L2 L3 L4 L8 L9 L10 L11 L12 L13 L14 L15 L16 L17 L18 L19 L20 L21 L22 L23 L24 against normal blind 12
fillet "Abrundung1" radius 2
chamfer "Fase2" distance 2
chamfer "Fase2" distance 0.6
sketch "Skizze7" plane through (0, 0, -2) normal (0, 0, -1) x axis (1, 0, 0)
  line L1 (78.95, -15.95) -> (73.75, -15.95)
  line L2 (78.95, 15.95) -> (78.95, -15.95)
  line L3 (73.75, 15.95) -> (78.95, 15.95)
  line L4 (73.75, 25.95) -> (73.75, 15.95)
  line L5 (78.95, 25.95) -> (73.75, 25.95)
  line L6 (-64.65, 40.25) -> (64.65, 40.25)
  line L7 (-78.95, -25.95) -> (-78.95, 25.95)
  line L8 (64.65, -40.25) -> (-64.65, -40.25)
  line L9 (73.75, -25.95) -> (78.95, -25.95)
  line L10 (73.75, -15.95) -> (73.75, -25.95)
  line L11 (8.15, -25) -> (28.15, -25)
  line L12 (8.15, -28.95) -> (8.15, -25)
  line L13 (-8.15, -28.95) -> (8.15, -28.95)
  line L14 (-8.15, -25) -> (-8.15, -28.95)
  line L15 (-28.15, -25) -> (-8.15, -25)
  line L16 (-28.15, -28.95) -> (-28.15, -25)
  line L17 (-64.65, -28.95) -> (-28.15, -28.95)
  line L18 (-67.65, 25.95) -> (-67.65, -25.95)
  line L19 (-28.15, 28.95) -> (-64.65, 28.95)
  line L20 (-28.15, 25) -> (-28.15, 28.95)
  line L21 (-8.15, 25) -> (-28.15, 25)
  line L22 (-8.15, 28.95) -> (-8.15, 25)
  line L23 (8.15, 28.95) -> (-8.15, 28.95)
  line L24 (8.15, 25) -> (8.15, 28.95)
  line L25 (28.15, 25) -> (8.15, 25)
  line L26 (28.15, 28.95) -> (28.15, 25)
  line L27 (64.65, 28.95) -> (28.15, 28.95)
  line L28 (67.65, -25.95) -> (67.65, 25.95)
  line L29 (28.15, -28.95) -> (64.65, -28.95)
  line L30 (28.15, -25) -> (28.15, -28.95)
  line L31 (-78.95, 8.4256) -> (-78.95, -8.4256)
  line L32 (-79.15, 25.95) -> (-79.15, 8.6551)
  line L33 (64.65, 40.45) -> (-64.65, 40.45)
  line L34 (83.0698, 29.95) -> (78.5874, 29.95)
  line L35 (80.4823, 31.8618) -> (83.0698, 29.95)
  line L36 (-64.65, 42.85) -> (64.65, 42.85)
  line L37 (-81.55, 19.2258) -> (-81.55, 25.95)
  line L38 (-95.35, 11.2583) -> (-81.55, 19.2258)
  line L39 (-81.55, -19.2258) -> (-95.35, -11.2583)
  line L40 (-81.55, -25.95) -> (-81.55, -19.2258)
  line L41 (64.65, -42.85) -> (-64.65, -42.85)
  line L42 (83.0698, -29.95) -> (80.4823, -31.8618)
  line L43 (78.5874, -29.95) -> (83.0698, -29.95)
  line L44 (-64.65, -40.45) -> (64.65, -40.45)
  line L45 (-79.15, -8.6551) -> (-79.15, -25.95)
  line L46 (-78.95, 19.2258) -> (-81.55, 19.2258)
  line L47 (-78.95, -19.2258) -> (-81.55, -19.2258)
  arc A1 centre (64.65, 25.95) radius 14.3 clockwise from (64.65, 40.25) to (78.95, 25.95)
  arc A2 centre (-64.65, 25.95) radius 14.3 clockwise from (-78.95, 25.95) to (-64.65, 40.25)
  arc A3 centre (-64.65, -25.95) radius 14.3 clockwise from (-64.65, -40.25) to (-78.95, -25.95)
  arc A4 centre (64.65, -25.95) radius 14.3 clockwise from (78.95, -25.95) to (64.65, -40.25)
  arc A5 centre (-64.65, -25.95) radius 3 clockwise from (-64.65, -28.95) to (-67.65, -25.95)
  arc A6 centre (-64.65, 25.95) radius 3 clockwise from (-67.65, 25.95) to (-64.65, 28.95)
  arc A7 centre (64.65, 25.95) radius 3 clockwise from (64.65, 28.95) to (67.65, 25.95)
  arc A8 centre (64.65, -25.95) radius 3 clockwise from (67.65, -25.95) to (64.65, -28.95)
  arc A9 centre (-88.85, 0) radius 13 clockwise from (-79.15, 8.6551) to (-78.95, 8.4256)
  arc A10 centre (-64.65, 25.95) radius 14.5 clockwise from (-79.15, 25.95) to (-64.65, 40.45)
  arc A11 centre (64.65, 25.95) radius 14.5 clockwise from (64.65, 40.45) to (78.5874, 29.95)
  arc A12 centre (64.65, 25.95) radius 16.9 clockwise from (64.65, 42.85) to (80.4823, 31.8618)
  arc A13 centre (-64.65, 25.95) radius 16.9 clockwise from (-81.55, 25.95) to (-64.65, 42.85)
  arc A14 centre (-88.85, 0) radius 13 clockwise from (-95.35, -11.2583) to (-95.35, 11.2583)
  arc A15 centre (-64.65, -25.95) radius 16.9 clockwise from (-64.65, -42.85) to (-81.55, -25.95)
  arc A16 centre (64.65, -25.95) radius 16.9 clockwise from (80.4823, -31.8618) to (64.65, -42.85)
  arc A17 centre (64.65, -25.95) radius 14.5 clockwise from (78.5874, -29.95) to (64.65, -40.45)
  arc A18 centre (-64.65, -25.95) radius 14.5 clockwise from (-64.65, -40.45) to (-79.15, -25.95)
  arc A19 centre (-88.85, 0) radius 13 clockwise from (-78.95, -8.4256) to (-79.15, -8.6551)
  circle C1 centre (-88.85, 0) radius 3
  point P59 (-81.55, 19.2258)
  point P75 (-81.55, 19.2258)
  point P76 (-78.95, 19.2258)
  point P62 (-81.55, -19.2258)
  point P77 (-81.55, -19.2258)
  point P78 (-78.95, -19.2258)
  coincident P59 P75
  coincident L7 P76
  perpendicular L7 L46
  coincident P62 P77
  coincident L7 P78
  perpendicular L7 L47
extrude "Extrusion6" add sketch "Skizze7" profile of L7 L31 A9 L32 L38 A14 L39 L45 A19 C1 L46 L47 to an object
remove_body "Körper entfernen3"
split "Teilen2"
remove_body "Körper entfernen4"
sketch "Skizze8" plane through (0, 0, -2) normal (0, 0, -1) x axis (1, 0, 0)
  line L1 (-79.15, 19.2258) -> (-81.55, 19.2258)
  line L2 (-79.15, 25.95) -> (-79.15, 19.2258)
  line L3 (64.65, 40.45) -> (-64.65, 40.45)
  line L4 (83.0698, 29.95) -> (78.5874, 29.95)
  line L5 (80.4823, 31.8618) -> (83.0698, 29.95)
  line L6 (-64.65, 42.85) -> (64.65, 42.85)
  line L7 (-81.55, 19.2258) -> (-81.55, 25.95)
  line L8 (-79.15, 19.2258) -> (-81.55, 19.2258)
  line L9 (-79.15, 19.4258) -> (-79.15, 19.2258)
  line L10 (-81.55, 19.4258) -> (-79.15, 19.4258)
  line L11 (-81.55, 19.2258) -> (-81.55, 19.4258)
  line L12 (-81.55, -19.2258) -> (-79.15, -19.2258)
  line L13 (-81.55, -25.95) -> (-81.55, -19.2258)
  line L14 (64.65, -42.85) -> (-64.65, -42.85)
  line L15 (83.0698, -29.95) -> (80.4823, -31.8618)
  line L16 (78.5874, -29.95) -> (83.0698, -29.95)
  line L17 (-64.65, -40.45) -> (64.65, -40.45)
  line L18 (-79.15, -19.2258) -> (-79.15, -25.95)
  line L19 (-79.15, -19.2258) -> (-81.55, -19.2258)
  line L20 (-79.15, -19.4258) -> (-79.15, -19.2258)
  line L21 (-81.55, -19.4258) -> (-79.15, -19.4258)
  line L22 (-81.55, -19.2258) -> (-81.55, -19.4258)
  arc A1 centre (-64.65, 25.95) radius 14.5 clockwise from (-79.15, 25.95) to (-64.65, 40.45)
  arc A2 centre (64.65, 25.95) radius 14.5 clockwise from (64.65, 40.45) to (78.5874, 29.95)
  arc A3 centre (64.65, 25.95) radius 16.9 clockwise from (64.65, 42.85) to (80.4823, 31.8618)
  arc A4 centre (-64.65, 25.95) radius 16.9 clockwise from (-81.55, 25.95) to (-64.65, 42.85)
  arc A5 centre (-64.65, -25.95) radius 16.9 clockwise from (-64.65, -42.85) to (-81.55, -25.95)
  arc A6 centre (64.65, -25.95) radius 16.9 clockwise from (80.4823, -31.8618) to (64.65, -42.85)
  arc A7 centre (64.65, -25.95) radius 14.5 clockwise from (78.5874, -29.95) to (64.65, -40.45)
  arc A8 centre (-64.65, -25.95) radius 14.5 clockwise from (-64.65, -40.45) to (-79.15, -25.95)
  point P17 (-79.15, 19.4258)
  point P2 (-81.55, 19.2258)
  point P15 (-81.55, 19.2258)
  point P34 (-79.15, -19.4258)
  point P20 (-81.55, -19.2258)
  point P32 (-81.55, -19.2258)
  point P35 (-81.55, -19.4258)
  horizontal L8
  vertical L9
  horizontal L10
  vertical L11
  coincident L2 P17
  coincident P2 P15
  horizontal L19
  vertical L20
  horizontal L21
  vertical L22
  coincident L18 P34
  coincident P20 P32
  dimension "d102" distance P34 P35 = 2.4
  dimension "d103" distance L19 L21 = 0.2
  dimension "d104" distance L8 L10 = 0.2 (= "d103")
extrude "Extrusion8" cut sketch "Skizze8" profile of L1 L2 L7 L8 L9 L10 L11 L12 L13 L18 L19 L20 L21 L22 to an object
sketch "Skizze8" plane through (0, 0, -2) normal (0, 0, -1) x axis (1, 0, 0)
  line L1 (78.95, -15.95) -> (73.75, -15.95)
  line L2 (78.95, 15.95) -> (78.95, -15.95)
  line L3 (73.75, 15.95) -> (78.95, 15.95)
  line L4 (73.75, 25.95) -> (73.75, 15.95)
  line L5 (78.95, 25.95) -> (73.75, 25.95)
  line L6 (-64.65, 40.25) -> (64.65, 40.25)
  line L7 (-78.95, 19.2258) -> (-78.95, 25.95)
  line L8 (-81.55, 19.2258) -> (-78.95, 19.2258)
  line L9 (-95.35, 11.2583) -> (-81.55, 19.2258)
  line L10 (-81.55, -19.2258) -> (-95.35, -11.2583)
  line L11 (-78.95, -19.2258) -> (-81.55, -19.2258)
  line L12 (-78.95, -25.95) -> (-78.95, -19.2258)
  line L13 (64.65, -40.25) -> (-64.65, -40.25)
  line L14 (73.75, -25.95) -> (78.95, -25.95)
  line L15 (73.75, -15.95) -> (73.75, -25.95)
  line L16 (8.15, -25) -> (28.15, -25)
  line L17 (8.15, -28.95) -> (8.15, -25)
  line L18 (-8.15, -28.95) -> (8.15, -28.95)
  line L19 (-8.15, -25) -> (-8.15, -28.95)
  line L20 (-28.15, -25) -> (-8.15, -25)
  line L21 (-28.15, -28.95) -> (-28.15, -25)
  line L22 (-64.65, -28.95) -> (-28.15, -28.95)
  line L23 (-67.65, 25.95) -> (-67.65, -25.95)
  line L24 (-28.15, 28.95) -> (-64.65, 28.95)
  line L25 (-28.15, 25) -> (-28.15, 28.95)
  line L26 (-8.15, 25) -> (-28.15, 25)
  line L27 (-8.15, 28.95) -> (-8.15, 25)
  line L28 (8.15, 28.95) -> (-8.15, 28.95)
  line L29 (8.15, 25) -> (8.15, 28.95)
  line L30 (28.15, 25) -> (8.15, 25)
  line L31 (28.15, 28.95) -> (28.15, 25)
  line L32 (64.65, 28.95) -> (28.15, 28.95)
  line L33 (67.65, -25.95) -> (67.65, 25.95)
  line L34 (28.15, -28.95) -> (64.65, -28.95)
  line L35 (28.15, -25) -> (28.15, -28.95)
  line L36 (-71.65, 25.95) -> (-71.65, -25.95)
  line L37 (-64.65, -32.95) -> (-24.15, -32.95)
  line L38 (-24.15, -32.95) -> (-24.15, -29)
  line L39 (-24.15, -29) -> (-12.15, -29)
  line L40 (-12.15, -29) -> (-12.15, -32.95)
  line L41 (-12.15, -32.95) -> (12.15, -32.95)
  line L42 (12.15, -32.95) -> (12.15, -29)
  line L43 (12.15, -29) -> (24.15, -29)
  line L44 (24.15, -29) -> (24.15, -32.95)
  line L45 (24.15, -32.95) -> (64.65, -32.95)
  line L46 (71.65, -25.95) -> (71.65, 25.95)
  line L47 (64.65, 32.95) -> (24.15, 32.95)
  line L48 (24.15, 32.95) -> (24.15, 29)
  line L49 (24.15, 29) -> (12.15, 29)
  line L50 (12.15, 29) -> (12.15, 32.95)
  line L51 (12.15, 32.95) -> (-12.15, 32.95)
  line L52 (-12.15, 32.95) -> (-12.15, 29)
  line L53 (-12.15, 29) -> (-24.15, 29)
  line L54 (-24.15, 29) -> (-24.15, 32.95)
  line L55 (-24.15, 32.95) -> (-64.65, 32.95)
  line L56 (-12.15, 32.95) -> (-24.15, 32.95)
  line L57 (24.15, 32.95) -> (12.15, 32.95)
  line L58 (-12.15, -32.95) -> (-24.15, -32.95)
  line L59 (24.15, -32.95) -> (12.15, -32.95)
  circle C1 centre (-88.85, 0) radius 3
  arc A1 centre (64.65, 25.95) radius 14.3 clockwise from (64.65, 40.25) to (78.95, 25.95)
  arc A2 centre (-64.65, 25.95) radius 14.3 clockwise from (-78.95, 25.95) to (-64.65, 40.25)
  arc A3 centre (-88.85, 0) radius 13 clockwise from (-95.35, -11.2583) to (-95.35, 11.2583)
  arc A4 centre (-64.65, -25.95) radius 14.3 clockwise from (-64.65, -40.25) to (-78.95, -25.95)
  arc A5 centre (64.65, -25.95) radius 14.3 clockwise from (78.95, -25.95) to (64.65, -40.25)
  arc A6 centre (-64.65, -25.95) radius 3 clockwise from (-64.65, -28.95) to (-67.65, -25.95)
  arc A7 centre (-64.65, 25.95) radius 3 clockwise from (-67.65, 25.95) to (-64.65, 28.95)
  arc A8 centre (64.65, 25.95) radius 3 clockwise from (64.65, 28.95) to (67.65, 25.95)
  arc A9 centre (64.65, -25.95) radius 3 clockwise from (67.65, -25.95) to (64.65, -28.95)
  arc A10 centre (-64.65, 25.95) radius 7 clockwise from (-71.65, 25.95) to (-64.65, 32.95)
  arc A11 centre (-64.65, -25.95) radius 7 clockwise from (-64.65, -32.95) to (-71.65, -25.95)
  arc A12 centre (64.65, -25.95) radius 7 clockwise from (71.65, -25.95) to (64.65, -32.95)
  arc A13 centre (64.65, 25.95) radius 7 clockwise from (64.65, 32.95) to (71.65, 25.95)
  dimension "d107" = -4
extrude "Extrusion7" add sketch "Skizze8" profile of L16 L17 L18 L19 L20 L21 L22 A6 L23 A7 L24 L25 L26 L27 L28 L29 L30 L31 L32 A8 L33 A9 L34 L35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 along normal blind 8
extrude "Extrusion8" add of existing geometry blind -15
sketch "Skizze9" plane through (0, 0, -2) normal (0, 0, -1) x axis (1, 0, 0)
  line L1 (78.95, 25.95) -> (71.65, 25.95)
  line L2 (-64.65, 40.25) -> (64.65, 40.25)
  line L3 (-78.95, 19.2258) -> (-78.95, 25.95)
  line L4 (-81.55, 19.2258) -> (-78.95, 19.2258)
  line L5 (-95.35, 11.2583) -> (-81.55, 19.2258)
  line L6 (-81.55, -19.2258) -> (-95.35, -11.2583)
  line L7 (-78.95, -19.2258) -> (-81.55, -19.2258)
  line L8 (-78.95, -25.95) -> (-78.95, -19.2258)
  line L9 (64.65, -40.25) -> (-64.65, -40.25)
  line L10 (71.65, -25.95) -> (78.95, -25.95)
  line L11 (-64.65, -32.95) -> (64.65, -32.95)
  line L12 (-71.65, 25.95) -> (-71.65, -25.95)
  line L13 (64.65, 32.95) -> (-64.65, 32.95)
  line L14 (-71.65, 10) -> (-88.85, 10)
  line L15 (-71.65, -10) -> (-88.85, -10)
  line L16 (71.65, 25.95) -> (71.65, -25.95)
  line L17 (-64.65, 32.95) -> (64.65, 32.95)
  line L18 (-71.65, -25.95) -> (-71.65, 25.95)
  line L19 (64.65, -32.95) -> (-64.65, -32.95)
  line L20 (28.15, -28.95) -> (64.65, -28.95)
  line L21 (28.15, -25) -> (28.15, -28.95)
  line L22 (8.15, -25) -> (28.15, -25)
  line L23 (8.15, -28.95) -> (8.15, -25)
  line L24 (-8.15, -28.95) -> (8.15, -28.95)
  line L25 (-8.15, -25) -> (-8.15, -28.95)
  line L26 (-28.15, -25) -> (-8.15, -25)
  line L27 (-28.15, -28.95) -> (-28.15, -25)
  line L28 (-64.65, -28.95) -> (-28.15, -28.95)
  line L29 (-67.65, 25.95) -> (-67.65, -25.95)
  line L30 (-28.15, 28.95) -> (-64.65, 28.95)
  line L31 (-28.15, 25) -> (-28.15, 28.95)
  line L32 (-8.15, 25) -> (-28.15, 25)
  line L33 (-8.15, 28.95) -> (-8.15, 25)
  line L34 (8.15, 28.95) -> (-8.15, 28.95)
  line L35 (8.15, 25) -> (8.15, 28.95)
  line L36 (28.15, 25) -> (8.15, 25)
  line L37 (28.15, 28.95) -> (28.15, 25)
  line L38 (64.65, 28.95) -> (28.15, 28.95)
  line L39 (67.65, -25.95) -> (67.65, 25.95)
  line L40 (-67.65, 10) -> (-71.65, 10)
  line L41 (-67.65, -10) -> (-71.65, -10)
  arc A1 centre (64.65, 25.95) radius 14.3 clockwise from (64.65, 40.25) to (78.95, 25.95)
  arc A2 centre (-64.65, 25.95) radius 14.3 clockwise from (-78.95, 25.95) to (-64.65, 40.25)
  arc A3 centre (-88.85, 0) radius 13 clockwise from (-95.35, -11.2583) to (-95.35, 11.2583)
  arc A4 centre (-64.65, -25.95) radius 14.3 clockwise from (-64.65, -40.25) to (-78.95, -25.95)
  arc A5 centre (64.65, -25.95) radius 14.3 clockwise from (78.95, -25.95) to (64.65, -40.25)
  circle C1 centre (-88.85, 0) radius 3
  circle C2 centre (-88.85, 0) radius 10
  arc A6 centre (64.65, -25.95) radius 7 clockwise from (71.65, -25.95) to (64.65, -32.95)
  arc A7 centre (-64.65, -25.95) radius 7 clockwise from (-64.65, -32.95) to (-71.65, -25.95)
  arc A8 centre (-64.65, 25.95) radius 7 clockwise from (-71.65, 25.95) to (-64.65, 32.95)
  arc A9 centre (64.65, 25.95) radius 7 clockwise from (64.65, 32.95) to (71.65, 25.95)
  arc A10 centre (64.65, 25.95) radius 7 clockwise from (64.65, 32.95) to (71.65, 25.95)
  arc A11 centre (-64.65, 25.95) radius 7 clockwise from (-71.65, 25.95) to (-64.65, 32.95)
  arc A12 centre (-64.65, -25.95) radius 7 clockwise from (-64.65, -32.95) to (-71.65, -25.95)
  arc A13 centre (64.65, -25.95) radius 7 clockwise from (71.65, -25.95) to (64.65, -32.95)
  arc A14 centre (64.65, -25.95) radius 3 clockwise from (67.65, -25.95) to (64.65, -28.95)
  arc A15 centre (-64.65, -25.95) radius 3 clockwise from (-64.65, -28.95) to (-67.65, -25.95)
  arc A16 centre (-64.65, 25.95) radius 3 clockwise from (-67.65, 25.95) to (-64.65, 28.95)
  arc A17 centre (64.65, 25.95) radius 3 clockwise from (64.65, 28.95) to (67.65, 25.95)
  point P30 (-88.85, 10)
  point P31 (-71.65, 10)
  point P32 (-88.85, -10)
  point P33 (-71.65, -10)
  point P71 (-67.65, 10)
  point P72 (-67.65, -10)
  concentric A3 C2
  coincident C2 P30
  coincident L12 P31
  perpendicular L12 L14
  coincident C2 P32
  coincident L12 P33
  perpendicular L12 L15
  tangent C2 L15
  tangent C2 L14
  coincident L29 P71
  perpendicular L29 L40
  coincident L29 P72
  perpendicular L29 L41
  dimension "d113" diameter C2 = 20
extrude "Extrusion9" add sketch "Skizze9" profile of C1 C2 L12 L14 L15 L18 L29 L40 L41 along normal blind 8
thread "Gewinde1"
chamfer "Fase4" distance 4
chamfer "Fase3" distance 2
sketch "Skizze10" plane through (-28.15, 0, 0) normal (-1, 0, 0) x axis (0, -1, 0)
  line L1 (25, -32) -> (14, -32)
  line L2 (25, -10) -> (25, -32)
  line L3 (28.95, -10) -> (25, -10)
  line L4 (28.95, 0) -> (28.95, -10)
  line L5 (-28.95, 0) -> (28.95, 0)
  line L6 (-28.95, -10) -> (-28.95, 0)
  line L7 (-25, -10) -> (-28.95, -10)
  line L8 (-25, -32) -> (-25, -10)
  line L9 (-14, -32) -> (-25, -32)
  line L10 (25.95, -10) -> (28.95, -10)
  line L11 (25, -10) -> (28.95, -10)
  line L12 (28.95, -10) -> (25, -10)
  line L13 (25, -10) -> (28.95, -10)
  line L14 (28.95, -10) -> (25, -10)
  line L15 (25.95, -10) -> (28.95, -10)
  line L16 (-25.95, -10) -> (25.95, -10)
  line L17 (-28.95, -10) -> (-25.95, -10)
  line L18 (-25, -10) -> (-28.95, -10)
  line L19 (-28.95, -10) -> (-25, -10)
  line L20 (-25, -10) -> (-28.95, -10)
  line L21 (-28.95, -10) -> (-25, -10)
  line L22 (-28.95, -10) -> (-25.95, -10)
  line L23 (25.95, -10) -> (-25.95, -10)
  line L24 (-25.95, -10) -> (-6, -10)
  line L25 (-25.95, -10) -> (-32.95, -10)
  line L26 (-25.95, -10) -> (-32.95, -10)
  line L27 (25.95, -10) -> (-25.95, -10)
  line L28 (32.95, -10) -> (25.95, -10)
  line L29 (32.95, -10) -> (25.95, -10)
  line L30 (-32.95, -10) -> (-25, -32)
  line L31 (25, -32) -> (32.95, -10)
  line L32 (6, -10) -> (25.95, -10)
  line L33 (-6, -10) -> (6, -10)
  line L34 (1.3629, -10) -> (-2.473, -10)
  line L35 (1.3629, -10) -> (2.117, -10)
  line L36 (-2.473, -10) -> (1.3629, -10)
  line L37 (-2.56, -10) -> (-2.473, -10)
  arc A1 centre (0, -32) radius 14 clockwise from (-14, -32) to (14, -32)
  point P12 (-25, -32)
  point P25 (-25, -32)
  point P23 (-32.95, -10)
  point P26 (-32.95, -10)
  point P24 (32.95, -10)
  point P27 (32.95, -10)
  point P5 (25, -32)
  point P28 (25, -32)
  coincident P12 P25
  coincident P23 P26
  coincident P24 P27
  coincident P5 P28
